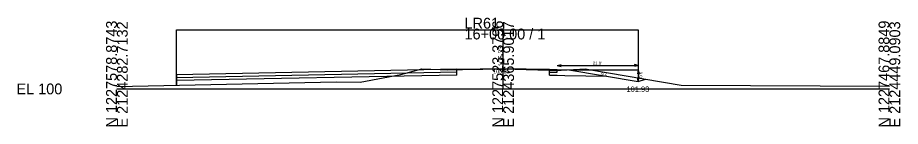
# Model space of a CAD drawing. Extents: x 2126751 to 2128979, y 1225108 to 1234639.
# Drawn here: x 2127750.9 to 2127979.4, y 1231107.5 to 1231135.7 of the extents above; entities that cross this region are included whole.
import ezdxf

# ---------------------------------------------------------------- set-up
doc = ezdxf.new("R2010")
doc.units = 0
for name, color, linetype in [('XS_CELL', 7, 'Continuous'), ('XS_M_DITCH', 7, 'Continuous'), ('XS_P_FINISHED_GRADE', 7, 'Continuous'), ('XS_P_FINISHED_GRADE_ELEV_TX', 7, 'Continuous'), ('XS_P_SUBGRADE_GRANULAR', 7, 'Continuous'), ('XS_P_SUBGRADE_LEVELING', 7, 'Continuous'), ('XS_P_SUBGRADE_PAVEMENT', 7, 'Continuous'), ('XS_P_TX_CLEARZONE', 7, 'Continuous'), ('XS_P_TX_DCH', 7, 'Continuous'), ('XS_P_TX_FS_BS', 7, 'Continuous'), ('XS_X_GROUND', 7, 'Continuous'), ('XS_X_GROUND_TX', 7, 'Continuous')]:
    doc.layers.add(name, color=color, linetype=linetype)

msp = doc.modelspace()

# ---------------------------------------------------------------- linework, layer by layer
at = {"layer": 'XS_CELL'}
for p, q in [((2127876.61, 1231117.21), (2127876.61, 1231132.83)), ((2127776.61, 1231117.21), (2127876.61, 1231117.21)), ((2127876.61, 1231117.21), (2127976.61, 1231117.21))]:
    msp.add_line(p, q, dxfattribs=at)
at = {"layer": 'XS_M_DITCH'}
for p, q in [((2127792.08, 1231118.16), (2127792.08, 1231132.54)), ((2127792.08, 1231132.54), (2127911.61, 1231132.54)), ((2127911.61, 1231132.54), (2127911.61, 1231119.14))]:
    msp.add_line(p, q, dxfattribs=at)
at = {"layer": 'XS_P_FINISHED_GRADE'}
for p, q in [((2127864.61, 1231122.3), (2127792.08, 1231120.85)), ((2127864.61, 1231122.3), (2127876.61, 1231122.54)), ((2127876.61, 1231122.54), (2127888.61, 1231122.3)), ((2127888.61, 1231122.3), (2127890.61, 1231122.26)), ((2127890.61, 1231122.26), (2127893.61, 1231122.14)), ((2127893.61, 1231122.14), (2127911.61, 1231119.14)), ((2127792.08, 1231120.85), (2127792.08, 1231118.16)), ((2127911.61, 1231119.14), (2127913.44, 1231119.75))]:
    msp.add_line(p, q, dxfattribs=at)
at = {"layer": 'XS_P_SUBGRADE_GRANULAR'}
for p, q in [((2127864.61, 1231120.8), (2127864.61, 1231121.55)), ((2127888.61, 1231120.8), (2127888.61, 1231121.55)), ((2127864.61, 1231120.8), (2127792.08, 1231119.35)), ((2127888.61, 1231120.8), (2127890.61, 1231120.76)), ((2127890.61, 1231120.76), (2127892.61, 1231120.72)), ((2127892.61, 1231120.72), (2127903.43, 1231120.5))]:
    msp.add_line(p, q, dxfattribs=at)
at = {"layer": 'XS_P_SUBGRADE_LEVELING'}
for p, q in [((2127864.61, 1231122.3), (2127864.61, 1231122.18)), ((2127864.61, 1231122.18), (2127866.06, 1231122.21)), ((2127866.06, 1231122.21), (2127876.61, 1231122.41)), ((2127876.61, 1231122.41), (2127888.54, 1231122.09)), ((2127888.54, 1231122.09), (2127888.61, 1231122.08)), ((2127888.61, 1231122.3), (2127888.61, 1231122.08))]:
    msp.add_line(p, q, dxfattribs=at)
at = {"layer": 'XS_P_SUBGRADE_PAVEMENT'}
for p, q in [((2127864.61, 1231121.55), (2127792.08, 1231120.1)), ((2127864.61, 1231121.55), (2127864.61, 1231122.18)), ((2127888.61, 1231121.55), (2127888.61, 1231122.08)), ((2127888.61, 1231121.55), (2127890.61, 1231121.51)), ((2127890.61, 1231121.51), (2127890.61, 1231122.26))]:
    msp.add_line(p, q, dxfattribs=at)
at = {"layer": 'XS_P_TX_CLEARZONE'}
for p, q in [((2127890.61, 1231123.26), (2127891.61, 1231123.51)), ((2127911.61, 1231123.26), (2127910.61, 1231123.51)), ((2127890.61, 1231123.26), (2127891.61, 1231123.01)), ((2127890.61, 1231123.26), (2127911.61, 1231123.26)), ((2127894.61, 1231122.14), (2127911.61, 1231122.14)), ((2127911.61, 1231123.26), (2127910.61, 1231123.01)), ((2127911.61, 1231122.14), (2127911.36, 1231121.14)), ((2127911.61, 1231122.14), (2127911.61, 1231119.14)), ((2127911.61, 1231122.14), (2127911.86, 1231121.14)), ((2127911.61, 1231119.14), (2127911.36, 1231120.14)), ((2127911.61, 1231119.14), (2127911.86, 1231120.14))]:
    msp.add_line(p, q, dxfattribs=at)
at = {"layer": 'XS_X_GROUND'}
for p, q in [((2127850.16, 1231120.97), (2127855.53, 1231122.39)), ((2127855.53, 1231122.39), (2127860.31, 1231122.22)), ((2127860.31, 1231122.22), (2127862.27, 1231122.14)), ((2127862.27, 1231122.14), (2127866.06, 1231122.21)), ((2127866.06, 1231122.21), (2127876.61, 1231122.41)), ((2127876.61, 1231122.41), (2127888.54, 1231122.09)), ((2127888.54, 1231122.09), (2127890.49, 1231122.02)), ((2127890.49, 1231122.02), (2127891.6, 1231122.09)), ((2127891.6, 1231122.09), (2127898.02, 1231122.39)), ((2127898.02, 1231122.39), (2127898.77, 1231122.21)), ((2127898.77, 1231122.21), (2127922.66, 1231118.21)), ((2127776.61, 1231117.83), (2127833.37, 1231119.01)), ((2127833.37, 1231119.01), (2127839.59, 1231118.93)), ((2127839.59, 1231118.93), (2127850.16, 1231120.97)), ((2127922.66, 1231118.21), (2127976.61, 1231117.93))]:
    msp.add_line(p, q, dxfattribs=at)

# ---------------------------------------------------------------- texts
at = {"layer": 'XS_CELL'}
for s, p in [('LR61', (2127866.61, 1231132.83)), ('16+00.00 / 1', (2127866.61, 1231130.03)), ('EL 100', (2127750.61, 1231115.81))]:
    msp.add_text(s, height=2.8, dxfattribs=at).set_placement(p)
for s, p in [('N 1227578.8743', (2127776.61, 1231107.21)), ('E 2124282.7132', (2127779.41, 1231107.21)), ('N 1227523.3796', (2127876.61, 1231107.21)), ('E 2124365.9017', (2127879.41, 1231107.21)), ('N 1227467.8849', (2127976.61, 1231107.21)), ('E 2124449.0903', (2127979.41, 1231107.21))]:
    msp.add_text(s, height=2.8, rotation=90, dxfattribs=at).set_placement(p)
at = {"layer": 'XS_P_FINISHED_GRADE_ELEV_TX'}
msp.add_text(' 105.33', height=1.25, rotation=90, dxfattribs=at).set_placement((2127876.61, 1231122.54))
at = {"layer": 'XS_P_TX_CLEARZONE'}
msp.add_text("21.0'", height=0.8, dxfattribs=at).set_placement((2127899.82, 1231123.46))
msp.add_text("3.0'", height=0.8, rotation=270, dxfattribs=at).set_placement((2127911.81, 1231121.67))
at = {"layer": 'XS_P_TX_DCH'}
msp.add_text('101.93', height=1.4, dxfattribs=at).set_placement((2127908.54, 1231116.44))
at = {"layer": 'XS_P_TX_FS_BS'}
msp.add_text('6:1', height=0.8, rotation=350.5377, dxfattribs=at).set_placement((2127901.95, 1231120.95))
at = {"layer": 'XS_X_GROUND_TX'}
msp.add_text('105.21', height=1, dxfattribs=at).set_placement((2127874.05, 1231121.25))

doc.saveas('drawing.dxf')
